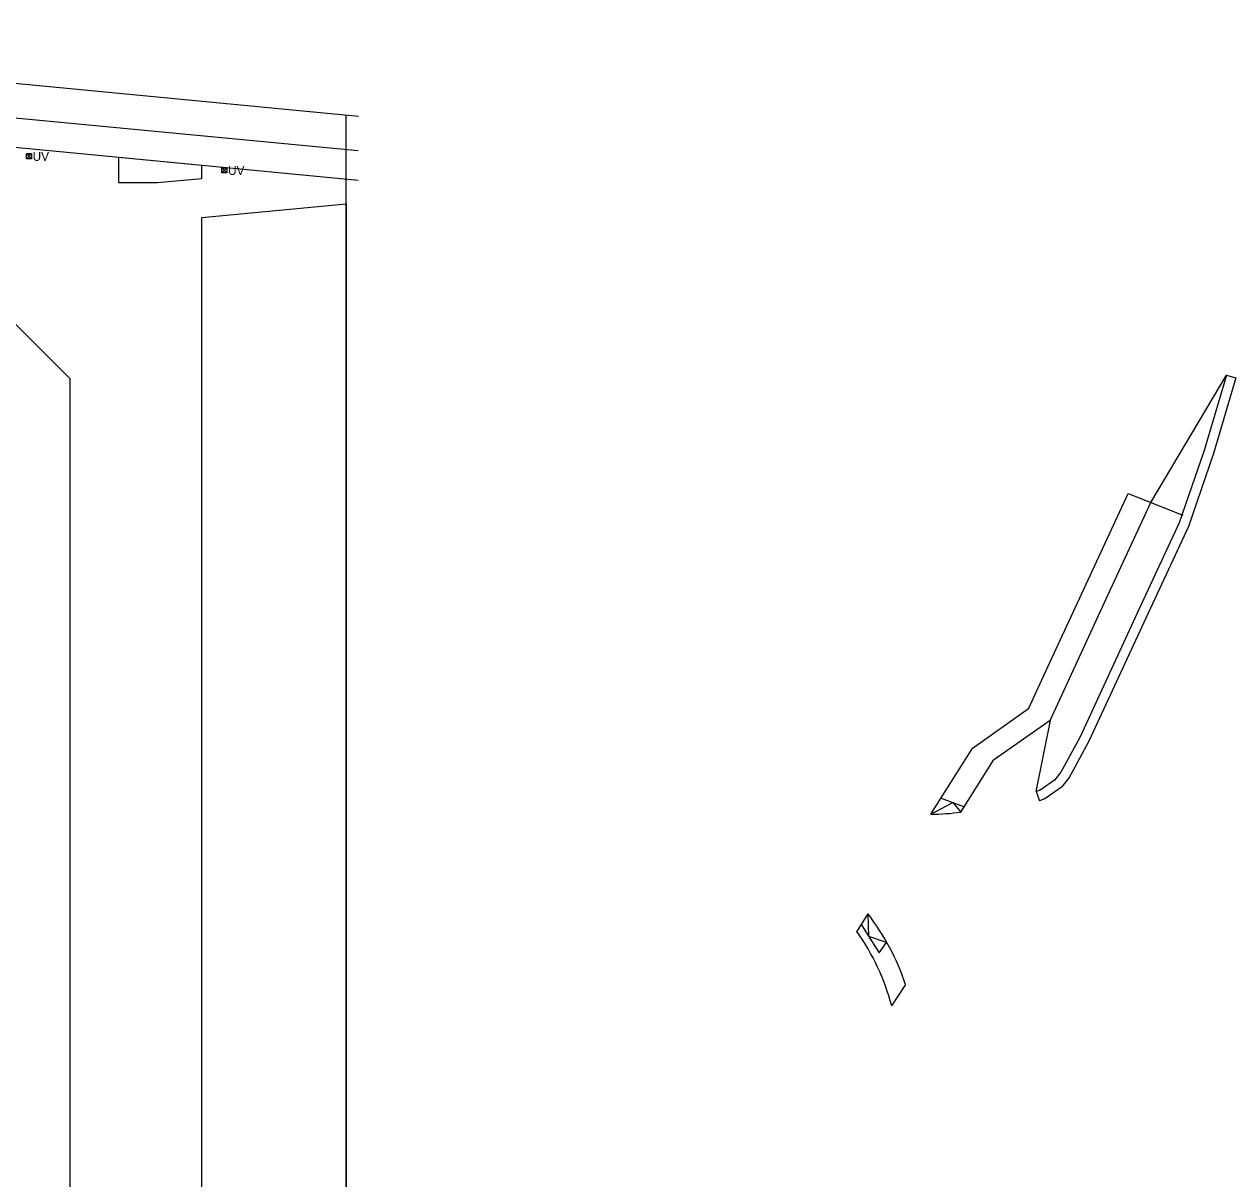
# Model space of a CAD drawing. Extents: x -264222 to -263676, y -1242344 to -1242060.
# Drawn here: x -263799.5 to -263675.5, y -1242183.3 to -1242065.1 of the extents above; entities that cross this region are included whole.
import ezdxf

# ---------------------------------------------------------------- set-up
doc = ezdxf.new("R2010")
doc.units = 0
doc.layers.add('PROJEKT_DRS_OBRUBNIKY_KOMUNIKACIE', color=7, linetype='Continuous')
doc.layers.add('PROJEKT_DRS_UV_STAVBY', color=7, linetype='Continuous')

msp = doc.modelspace()

# ---------------------------------------------------------------- linework, layer by layer
at = {"layer": 'PROJEKT_DRS_OBRUBNIKY_KOMUNIKACIE'}
for p, q in [((-263765.32, -1242074.56), (-263863.95, -1242065.11)), ((-263765.36, -1242078.08), (-263864.28, -1242068.59)), ((-263765.37, -1242081.09), (-263864.57, -1242071.58)), ((-263766.58, -1242144.85), (-263766.58, -1242074.39)), ((-263781.37, -1242079.56), (-263789.89, -1242078.74)), ((-263789.89, -1242078.74), (-263789.89, -1242081.31)), ((-263781.37, -1242080.9), (-263781.37, -1242079.56)), ((-263789.89, -1242081.31), (-263785.89, -1242081.31)), ((-263785.89, -1242081.31), (-263781.37, -1242080.9)), ((-263684.23, -1242114.08), (-263676.51, -1242101.02)), ((-263676.51, -1242101.02), (-263675.55, -1242101.3)), ((-263696.75, -1242135.18), (-263702.54, -1242139.27)), ((-263694.55, -1242136.37), (-263700.33, -1242140.45)), ((-263695.98, -1242143.65), (-263694.52, -1242136.39)), ((-263706.76, -1242145.97), (-263702.54, -1242139.27)), ((-263703.67, -1242145.76), (-263700.33, -1242140.45)), ((-263705.79, -1242144.3), (-263703.32, -1242145.21)), ((-263695.98, -1242143.65), (-263695.64, -1242144.59)), ((-263766.58, -1242201.01), (-263766.58, -1242144.85)), ((-263714.32, -1242158), (-263713.18, -1242156.18)), ((-263710.76, -1242165.59), (-263709.33, -1242163.41))]:
    msp.add_line(p, q, dxfattribs=at)
for points in [[(-263766.58, -1242083.48), (-263766.58, -1242201.01), (-263749.88, -1242212.11), (-263758.15, -1242224.37), (-263781.36, -1242208.94), (-263781.37, -1242084.9), (-263766.58, -1242083.48)], [(-263794.89, -1242227.38), (-263808.97, -1242241.46), (-263894.97, -1242241.46), (-263909.04, -1242227.38), (-263909.04, -1242196.33), (-263914.14, -1242196.33), (-263914.14, -1242132.43), (-263909.04, -1242132.43), (-263909.04, -1242101.38), (-263894.97, -1242087.31), (-263808.97, -1242087.31), (-263794.89, -1242101.38), (-263794.89, -1242227.38)], [(-263676.51, -1242101.02), (-263678.79, -1242108.75), (-263681.33, -1242116.16), (-263685.42, -1242124.96), (-263691.48, -1242138.04), (-263692.91, -1242140.69), (-263693.44, -1242141.67), (-263694.09, -1242142.48), (-263695.56, -1242143.5), (-263695.98, -1242143.65)], [(-263675.55, -1242101.3), (-263677.84, -1242109.05), (-263680.4, -1242116.53), (-263684.51, -1242125.38), (-263690.58, -1242138.49), (-263692.03, -1242141.17), (-263692.61, -1242142.22), (-263693.4, -1242143.22), (-263695.1, -1242144.4), (-263695.64, -1242144.59)], [(-263696.75, -1242135.18), (-263694.58, -1242130.46), (-263690.86, -1242122.43), (-263686.56, -1242113.16), (-263680.98, -1242115.36)], [(-263694.55, -1242136.37), (-263692.37, -1242131.64), (-263688.6, -1242123.5), (-263684.23, -1242114.08)], [(-263706.76, -1242145.97), (-263704.52, -1242144.77), (-263703.67, -1242145.76)], [(-263713.89, -1242157.25), (-263712.03, -1242160.15), (-263711.29, -1242159.12), (-263713.09, -1242158.51), (-263713.18, -1242156.18)]]:
    msp.add_lwpolyline(points, dxfattribs=at)
for centre, radius, start, end in [((-263706.75, -1242123.94), 22.03, 269.9755, 278.0376), ((-263733.41, -1242171.59), 25.43, 18.7653, 37.3002), ((-263733.41, -1242171.59), 23.43, 14.8336, 35.4575)]:
    msp.add_arc(centre, radius, start, end, dxfattribs=at)
at = {"layer": 'PROJEKT_DRS_UV_STAVBY'}
for points in [[(-263799.31, -1242078.88), (-263799.31, -1242078.38), (-263798.81, -1242078.38), (-263798.81, -1242078.88), (-263799.31, -1242078.88), (-263798.81, -1242078.38), (-263799.31, -1242078.38), (-263798.81, -1242078.88)], [(-263779.32, -1242080.31), (-263779.32, -1242079.81), (-263778.82, -1242079.81), (-263778.82, -1242080.31), (-263779.32, -1242080.31), (-263778.82, -1242079.81), (-263779.32, -1242079.81), (-263778.82, -1242080.31)]]:
    msp.add_lwpolyline(points, dxfattribs=at)

# ---------------------------------------------------------------- texts
for p in [(-263798.68, -1242079.09), (-263778.68, -1242080.53)]:
    msp.add_text('UV', height=0.9, rotation=359.8587, dxfattribs=at).set_placement(p)

doc.saveas('drawing.dxf')
